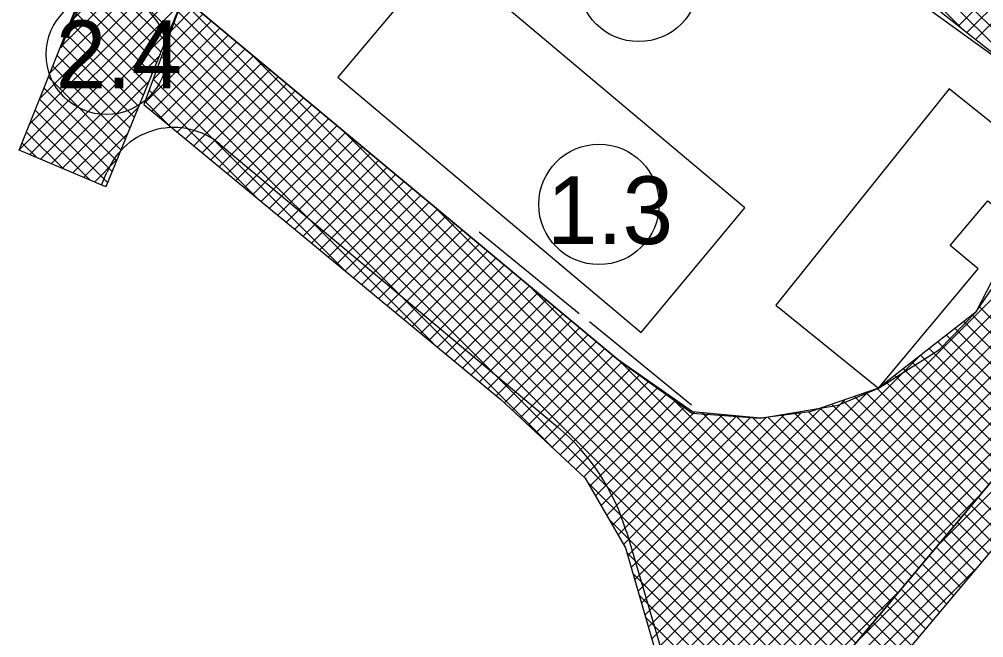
# Model space of a CAD drawing. Extents: x -438410 to -437811, y -1133174 to -1132817.
# Drawn here: x -438157.89 to -438131.22, y -1132971.41 to -1132954.3 of the extents above; entities that cross this region are included whole.
import ezdxf

# ---------------------------------------------------------------- set-up
doc = ezdxf.new("R2010")
doc.units = 0
for name, color, linetype in [('10 - legenda', 7, 'Continuous'), ('Vrstva 1', 7, 'Continuous'), ('Vrstva 5', 7, 'Continuous')]:
    doc.layers.add(name, color=color, linetype=linetype)

msp = doc.modelspace()

# ---------------------------------------------------------------- linework, layer by layer
at = {"layer": '10 - legenda'}
for p, q in [((-438156.76, -1132955.077), (-438148.729, -1132947.046)), ((-438156.479, -1132954.372), (-438149.161, -1132947.054)), ((-438134.594, -1132950.937), (-438120.304, -1132965.228)), ((-438134.74, -1132951.216), (-438119.886, -1132966.07)), ((-438134.885, -1132951.495), (-438131.82, -1132954.56)), ((-438157.042, -1132955.783), (-438153.321, -1132952.062)), ((-438157.323, -1132956.489), (-438153.466, -1132952.631)), ((-438155.759, -1132952.565), (-438153.732, -1132954.591)), ((-438155.88, -1132952.869), (-438153.855, -1132954.893)), ((-438157.605, -1132957.194), (-438153.517, -1132953.107)), ((-438156, -1132953.172), (-438153.978, -1132955.194)), ((-438131.923, -1132954.479), (-438130.544, -1132953.1)), ((-438131.686, -1132954.666), (-438130.308, -1132953.288)), ((-438157.886, -1132957.9), (-438153.427, -1132953.441)), ((-438156.121, -1132953.475), (-438154.101, -1132955.496)), ((-438131.449, -1132954.853), (-438130.072, -1132953.476)), ((-438157.605, -1132958.043), (-438153.443, -1132953.881)), ((-438156.242, -1132953.779), (-438154.224, -1132955.797)), ((-438153.395, -1132953.774), (-438135.149, -1132972.02)), ((-438156.363, -1132954.082), (-438154.347, -1132956.098)), ((-438153.949, -1132955.292), (-438152.805, -1132954.148)), ((-438153.705, -1132954.624), (-438153.036, -1132953.955)), ((-438153.509, -1132954.085), (-438135.343, -1132972.251)), ((-438156.484, -1132954.385), (-438154.47, -1132956.4)), ((-438154.193, -1132955.96), (-438152.574, -1132954.34)), ((-438153.622, -1132954.396), (-438135.536, -1132972.482)), ((-438157.307, -1132958.169), (-438153.735, -1132954.597)), ((-438156.605, -1132954.688), (-438154.593, -1132956.701)), ((-438154.437, -1132956.628), (-438152.342, -1132954.533)), ((-438154.226, -1132956.841), (-438152.111, -1132954.726)), ((-438153.994, -1132957.033), (-438151.88, -1132954.919)), ((-438153.736, -1132954.706), (-438135.73, -1132972.712)), ((-438156.726, -1132954.992), (-438154.716, -1132957.002)), ((-438153.849, -1132955.017), (-438135.923, -1132972.943)), ((-438153.761, -1132957.225), (-438151.648, -1132955.112)), ((-438151.555, -1132955.19), (-438134.956, -1132971.789)), ((-438157.009, -1132958.296), (-438154.027, -1132955.314)), ((-438156.847, -1132955.295), (-438154.839, -1132957.304)), ((-438153.962, -1132955.328), (-438143.028, -1132966.262)), ((-438153.529, -1132957.417), (-438151.417, -1132955.305)), ((-438156.968, -1132955.598), (-438154.962, -1132957.605)), ((-438154.076, -1132955.639), (-438146.443, -1132963.272)), ((-438153.297, -1132957.609), (-438151.186, -1132955.498)), ((-438153.064, -1132957.801), (-438150.954, -1132955.691)), ((-438157.089, -1132955.902), (-438155.084, -1132957.906)), ((-438154.189, -1132955.95), (-438148.885, -1132961.254)), ((-438152.832, -1132957.993), (-438150.723, -1132955.884)), ((-438157.21, -1132956.205), (-438155.207, -1132958.208)), ((-438156.711, -1132958.422), (-438154.319, -1132956.03)), ((-438154.303, -1132956.26), (-438151.327, -1132959.237)), ((-438152.6, -1132958.185), (-438150.492, -1132956.077)), ((-438152.367, -1132958.377), (-438150.26, -1132956.27)), ((-438157.331, -1132956.508), (-438155.33, -1132958.509)), ((-438152.135, -1132958.569), (-438150.029, -1132956.463)), ((-438157.452, -1132956.812), (-438155.453, -1132958.81)), ((-438156.413, -1132958.549), (-438154.612, -1132956.747)), ((-438154.416, -1132956.571), (-438153.768, -1132957.219)), ((-438151.903, -1132958.761), (-438149.798, -1132956.656)), ((-438151.67, -1132958.953), (-438149.566, -1132956.848)), ((-438151.438, -1132959.145), (-438149.335, -1132957.041)), ((-438157.573, -1132957.115), (-438155.937, -1132958.751)), ((-438151.206, -1132959.337), (-438149.104, -1132957.234)), ((-438148.999, -1132957.321), (-438134.762, -1132971.558)), ((-438140.401, -1132971.442), (-438126.153, -1132957.194)), ((-438157.694, -1132957.418), (-438156.674, -1132958.438)), ((-438156.116, -1132958.675), (-438154.904, -1132957.463)), ((-438150.973, -1132959.528), (-438148.872, -1132957.427)), ((-438150.741, -1132959.72), (-438148.641, -1132957.62)), ((-438140.306, -1132971.772), (-438125.946, -1132957.411)), ((-438140.212, -1132972.101), (-438125.738, -1132957.627)), ((-438157.815, -1132957.722), (-438157.412, -1132958.125)), ((-438150.509, -1132959.912), (-438148.41, -1132957.813)), ((-438140.117, -1132972.431), (-438125.53, -1132957.844)), ((-438150.277, -1132960.104), (-438148.178, -1132958.006)), ((-438140.022, -1132972.76), (-438125.323, -1132958.061)), ((-438155.818, -1132958.802), (-438155.196, -1132958.18)), ((-438150.044, -1132960.296), (-438147.947, -1132958.199)), ((-438149.812, -1132960.488), (-438147.716, -1132958.392)), ((-438139.928, -1132973.09), (-438125.115, -1132958.277)), ((-438149.58, -1132960.68), (-438147.484, -1132958.585)), ((-438139.833, -1132973.419), (-438124.907, -1132958.494)), ((-438155.52, -1132958.928), (-438155.488, -1132958.896)), ((-438149.347, -1132960.872), (-438147.253, -1132958.778)), ((-438139.736, -1132973.747), (-438124.7, -1132958.711)), ((-438139.501, -1132973.936), (-438124.492, -1132958.927)), ((-438149.115, -1132961.064), (-438147.022, -1132958.971)), ((-438148.883, -1132961.256), (-438146.79, -1132959.164)), ((-438139.265, -1132974.125), (-438124.285, -1132959.144)), ((-438148.65, -1132961.448), (-438146.559, -1132959.357)), ((-438146.444, -1132959.452), (-438134.569, -1132971.328)), ((-438139.03, -1132974.314), (-438124.096, -1132959.379)), ((-438148.418, -1132961.64), (-438146.328, -1132959.549)), ((-438148.186, -1132961.832), (-438146.096, -1132959.742)), ((-438138.795, -1132974.503), (-438123.911, -1132959.618)), ((-438147.953, -1132962.024), (-438145.865, -1132959.935)), ((-438147.721, -1132962.216), (-438145.634, -1132960.128)), ((-438145.172, -1132960.177), (-438142.409, -1132962.434)), ((-438147.489, -1132962.408), (-438145.402, -1132960.321)), ((-438147.256, -1132962.6), (-438145.171, -1132960.514)), ((-438147.024, -1132962.792), (-438144.939, -1132960.707)), ((-438146.792, -1132962.984), (-438144.708, -1132960.9)), ((-438146.559, -1132963.176), (-438144.477, -1132961.093)), ((-438146.327, -1132963.367), (-438144.245, -1132961.286)), ((-438146.095, -1132963.559), (-438144.014, -1132961.479)), ((-438143.889, -1132961.583), (-438134.375, -1132971.097)), ((-438145.863, -1132963.751), (-438143.783, -1132961.672)), ((-438145.63, -1132963.943), (-438143.551, -1132961.865)), ((-438145.398, -1132964.135), (-438143.32, -1132962.057)), ((-438145.166, -1132964.327), (-438143.089, -1132962.25)), ((-438131.356, -1132962.237), (-438109.681, -1132983.912)), ((-438144.933, -1132964.519), (-438142.857, -1132962.443)), ((-438144.701, -1132964.711), (-438142.626, -1132962.636)), ((-438142.123, -1132962.663), (-438139.301, -1132964.969)), ((-438131.777, -1132962.664), (-438110.067, -1132984.374)), ((-438131.539, -1132962.478), (-438109.874, -1132984.143)), ((-438144.475, -1132964.909), (-438142.395, -1132962.829)), ((-438132.015, -1132962.85), (-438110.26, -1132984.605)), ((-438144.255, -1132965.114), (-438142.163, -1132963.022)), ((-438144.036, -1132965.319), (-438141.932, -1132963.215)), ((-438132.492, -1132963.222), (-438110.646, -1132985.068)), ((-438132.254, -1132963.036), (-438110.453, -1132984.837)), ((-438143.817, -1132965.524), (-438141.701, -1132963.408)), ((-438132.73, -1132963.408), (-438110.839, -1132985.299)), ((-438143.598, -1132965.729), (-438141.469, -1132963.601)), ((-438141.334, -1132963.714), (-438134.182, -1132970.866)), ((-438140.496, -1132971.113), (-438133.008, -1132963.625)), ((-438132.969, -1132963.594), (-438112.542, -1132984.021)), ((-438143.379, -1132965.934), (-438141.231, -1132963.787)), ((-438143.159, -1132966.139), (-438140.982, -1132963.962)), ((-438133.445, -1132963.966), (-438127.28, -1132970.131)), ((-438133.207, -1132963.78), (-438124.602, -1132972.384)), ((-438142.94, -1132966.345), (-438140.732, -1132964.137)), ((-438133.683, -1132964.152), (-438129.958, -1132967.878)), ((-438142.721, -1132966.55), (-438140.483, -1132964.312)), ((-438142.502, -1132966.755), (-438140.234, -1132964.487)), ((-438134.168, -1132964.516), (-438131.279, -1132967.405)), ((-438133.922, -1132964.338), (-438131.086, -1132967.174)), ((-438142.283, -1132966.96), (-438139.984, -1132964.661)), ((-438140.685, -1132970.454), (-438135.052, -1132964.821)), ((-438140.591, -1132970.783), (-438134.405, -1132964.598)), ((-438139.91, -1132964.714), (-438133.988, -1132970.635)), ((-438134.799, -1132964.733), (-438131.666, -1132967.866)), ((-438134.483, -1132964.625), (-438131.473, -1132967.635)), ((-438142.116, -1132967.217), (-438139.735, -1132964.836)), ((-438141.96, -1132967.485), (-438139.486, -1132965.011)), ((-438140.78, -1132970.124), (-438135.699, -1132965.043)), ((-438135.746, -1132965.059), (-438132.247, -1132968.559)), ((-438135.43, -1132964.951), (-438132.053, -1132968.328)), ((-438135.115, -1132964.842), (-438131.86, -1132968.097)), ((-438141.804, -1132967.754), (-438139.213, -1132965.163)), ((-438141.648, -1132968.022), (-438138.825, -1132965.199)), ((-438141.492, -1132968.291), (-438138.437, -1132965.236)), ((-438141.336, -1132968.559), (-438138.049, -1132965.272)), ((-438141.181, -1132968.828), (-438137.661, -1132965.308)), ((-438141.064, -1132969.135), (-438137.242, -1132965.313)), ((-438140.97, -1132969.465), (-438136.755, -1132965.25)), ((-438140.875, -1132969.795), (-438136.268, -1132965.188)), ((-438139.018, -1132965.181), (-438133.795, -1132970.405)), ((-438138.55, -1132965.225), (-438133.601, -1132970.174)), ((-438138.082, -1132965.269), (-438133.408, -1132969.943)), ((-438137.614, -1132965.313), (-438133.214, -1132969.712)), ((-438137.195, -1132965.307), (-438133.021, -1132969.482)), ((-438136.819, -1132965.259), (-438132.827, -1132969.251)), ((-438136.443, -1132965.21), (-438132.634, -1132969.02)), ((-438136.068, -1132965.162), (-438132.44, -1132968.789)), ((-438142.174, -1132967.116), (-438136.117, -1132973.174)), ((-438132.515, -1132968.879), (-438130.803, -1132967.166)), ((-438138.559, -1132974.692), (-438131.314, -1132967.446)), ((-438134.718, -1132971.506), (-438130.572, -1132967.36)), ((-438137.727, -1132975.364), (-438130.112, -1132967.748)), ((-438136.921, -1132974.133), (-438130.342, -1132967.554)), ((-438131.572, -1132967.754), (-438129.213, -1132970.113)), ((-438131.379, -1132967.523), (-438126.655, -1132972.247)), ((-438131.766, -1132967.985), (-438130.887, -1132968.863)), ((-438141.587, -1132968.128), (-438136.31, -1132973.405)), ((-438131.959, -1132968.216), (-438131.081, -1132969.094)), ((-438132.153, -1132968.446), (-438131.275, -1132969.324)), ((-438132.346, -1132968.677), (-438131.468, -1132969.555)), ((-438141.089, -1132969.05), (-438136.504, -1132973.635)), ((-438132.54, -1132968.908), (-438131.662, -1132969.785)), ((-438132.733, -1132969.139), (-438131.856, -1132970.016)), ((-438137.496, -1132975.557), (-438131.333, -1132969.394)), ((-438133.12, -1132969.6), (-438132.243, -1132970.477)), ((-438132.927, -1132969.369), (-438132.049, -1132970.247)), ((-438140.918, -1132969.646), (-438136.697, -1132973.866)), ((-438133.314, -1132969.831), (-438132.437, -1132970.708)), ((-438138.324, -1132974.88), (-438133.517, -1132970.073)), ((-438133.507, -1132970.062), (-438132.631, -1132970.938)), ((-438140.746, -1132970.241), (-438136.891, -1132974.097)), ((-438133.701, -1132970.292), (-438132.824, -1132971.169)), ((-438133.894, -1132970.523), (-438133.018, -1132971.399)), ((-438140.575, -1132970.837), (-438137.084, -1132974.328)), ((-438134.088, -1132970.754), (-438133.212, -1132971.63)), ((-438134.475, -1132971.216), (-438133.599, -1132972.091)), ((-438134.281, -1132970.985), (-438133.405, -1132971.861))]:
    msp.add_line(p, q, dxfattribs=at)
for points in [[(-438153.362, -1132953.683), (-438141.329, -1132963.718), (-438139.289, -1132965.196), (-438137.396, -1132965.333), (-438135.25, -1132964.978), (-438134.136, -1132964.505), (-438132.444, -1132963.434), (-438131.441, -1132962.402), (-438130.504, -1132961.025), (-438129.696, -1132959.017), (-438129.592, -1132957.446), (-438129.905, -1132956.074), (-438133.603, -1132953.391), (-438137.63, -1132951.233), (-438141.796, -1132949.8), (-438144.368, -1132949.286), (-438146.02, -1132949.095), (-438148.81, -1132949.169), (-438151.016, -1132949.704), (-438152.461, -1132950.801), (-438153.127, -1132951.692), (-438153.435, -1132952.654), (-438153.553, -1132952.973)], [(-438136.916, -1132976.04), (-438130.815, -1132968.777), (-438122.743, -1132975.51), (-438121.978, -1132974.593), (-438130.965, -1132967.03), (-438137.86, -1132975.253)]]:
    msp.add_lwpolyline(points, close=True, dxfattribs=at)
for points in [[(-438128.583, -1132954.659), (-438131.681, -1132952.197), (-438134.379, -1132950.526), (-438135.315, -1132952.317), (-438132.442, -1132954.068), (-438129.905, -1132956.074)], [(-438153.362, -1132953.683), (-438155.504, -1132958.935), (-438157.894, -1132957.92), (-438155.415, -1132951.704)], [(-438129.69, -1132959.007), (-438131.441, -1132962.402), (-438134.136, -1132964.505), (-438136.029, -1132965.157), (-438137.396, -1132965.333), (-438139.278, -1132965.157), (-438141.329, -1132963.718), (-438153.362, -1132953.683), (-438154.448, -1132956.658), (-438144.574, -1132964.816), (-438142.244, -1132966.996), (-438141.125, -1132968.923), (-438139.739, -1132973.744)], [(-438137.86, -1132975.253), (-438130.965, -1132967.03), (-438121.978, -1132974.593)]]:
    msp.add_lwpolyline(points, dxfattribs=at)
for centre in [(-438140.765, -1132953.25), (-438155.482, -1132955.268), (-438141.863, -1132959.42)]:
    msp.add_circle(centre, 1.666, dxfattribs=at)
at = {"layer": 'Vrstva 1'}
for p, q in [((-438152.337, -1132957.758), (-438143.007, -1132965.574)), ((-438155.619, -1132958.886), (-438155.469, -1132958.525)), ((-438141.105, -1132968.475), (-438139.515, -1132973.862))]:
    msp.add_line(p, q, dxfattribs=at)
for points in [[(-438146.195, -1132952.465), (-438149.086, -1132955.896), (-438140.7, -1132962.963), (-438137.833, -1132959.512)], [(-438132.181, -1132956.223), (-438136.968, -1132962.209), (-438134.136, -1132964.505), (-438131.375, -1132961.204), (-438132.148, -1132960.557), (-438131.114, -1132959.322), (-438130.348, -1132959.977), (-438129.211, -1132958.606)]]:
    msp.add_lwpolyline(points, close=True, dxfattribs=at)
for centre, radius, start, end in [((-438319.728, -1132891.239), 175.056, 338.61587, 350.60351), ((-438145.627, -1132959.601), 12, 68.8995, 157.9324), ((-438153.621, -1132959.291), 2, 50.0448, 157.4689), ((-438146.86, -1132970.174), 6, 16.4456, 50.0448)]:
    msp.add_arc(centre, radius, start, end, dxfattribs=at)

# ---------------------------------------------------------------- texts
at = {"layer": 'Vrstva 5'}
for s, p in [('2.4', (-438156.882, -1132956.206)), ('1.3', (-438143.301, -1132960.52))]:
    msp.add_text(s, height=1.875, dxfattribs=at).set_placement(p)

doc.saveas('drawing.dxf')
